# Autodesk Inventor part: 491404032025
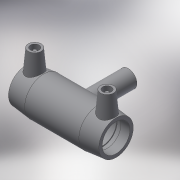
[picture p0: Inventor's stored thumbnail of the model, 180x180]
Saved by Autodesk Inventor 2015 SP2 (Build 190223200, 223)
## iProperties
Created: 2017-06
Part Number: 491404032025
Material: Generic
Description: PLASSON REDUCING TEE 32x25x32
Document SubType Name: Modeling
Designer: KIM
Mass: 57.3761 g
Surface Area: 241.06 cm^2
Volume: 57.3761 cm^3
Density: 1 g/cm^3
Appearance: Default
Author: KIM
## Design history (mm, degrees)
derived "491404.ipt"
feature "Solid1::491404.ipt"
tag "TaggingFeature1"
body "Solid1"
other parameters: "d0" = 104, "d1" = 32, "d2" = 44, "d3" = 39, "d4" = 20.8, "d5" = 39.6, "d6" = 30.4, "d7" = 32, "d8" = 168 deg, "d10" = 15.6, "d11" = 5.2, "d13" = 104, "d14" = 17.6296, "d17" = 28.8, "d18" = 32, "d19" = 3.52592, "d20" = 168 deg, "d22" = 40.92, "d23" = 44, "d25" = 135 deg, "d26" = 72.8, "d29" = 43, "d30" = 15, "d31" = 41.6, "d34" = 5 deg, "d35" = 15, "d39" = 5 deg, "d41" = 4, "d42" = 14, "d43" = 0, "d45" = 4, "d46" = 6, "d47" = 0, "d48" = -66, "d49" = 25, "d51" = 0, "d54" = 0, "d55" = 39.6, "d56" = 44, "d57" = 36.4, "d58" = 135 deg, "d59" = 39, "d60" = 39, "d61" = 135 deg, "d62" = 66, "d72" = 47.32, "d73" = 23.66, "d74" = -66, "d75" = 26.25, "d77" = 0, "d80" = 0, "d81" = 25, "d82" = 44, "d83" = 0, "d84" = 3, "d85" = 0, "d86" = 13, "d87" = 40.1016, "d88" = 5.2, "d89" = 3, "d90" = 0, "d_" = 32, "L_" = 104, "L_1" = 39, "D_" = 44, "A_" = 43, "d_2" = 12, "H_" = 66, "d_1" = 25
